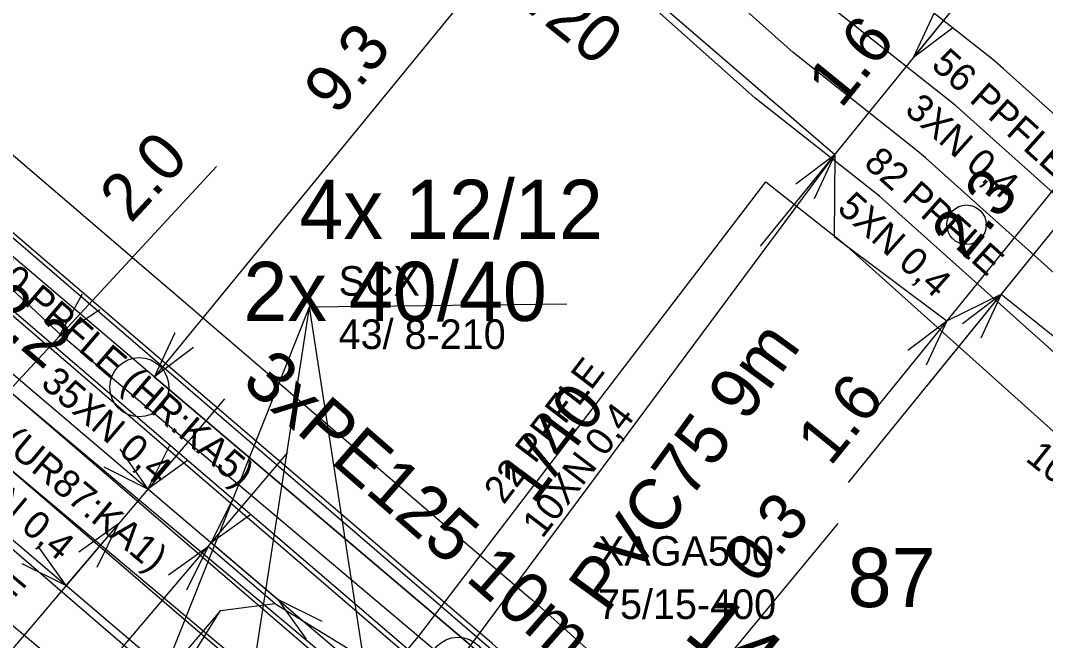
# Model space of a CAD drawing. Extents: x -756413 to -755757, y -1139003 to -1138237.
# Drawn here: x -756288.54 to -756275.54, y -1138375.06 to -1138367.2 of the extents above; entities that cross this region are included whole.
import ezdxf

# ---------------------------------------------------------------- set-up
doc = ezdxf.new("R2010")
doc.units = 0
for name, color, linetype in [('f001_pol_znacky', 7, 'Continuous'), ('f002_inz_znacky_mimo_TO2', 7, 'Continuous'), ('f004_popis_kab_zil', 7, 'Continuous'), ('f004_popisy_mts', 7, 'Continuous'), ('f004_rozvadec_ann', 7, 'Continuous'), ('f006_osa_trasy', 7, 'Continuous'), ('f006_stp_koty', 7, 'Continuous'), ('f006_stp_linie', 7, 'Continuous'), ('f006_stp_texty', 7, 'Continuous'), ('f307_kabel_metal', 7, 'Continuous'), ('f307_kabel_metal_ann', 7, 'Continuous'), ('f307_spojka_metal_ann', 7, 'Continuous'), ('f309_trubka', 7, 'Continuous'), ('f373_cerch_cara', 7, 'Continuous')]:
    doc.layers.add(name, color=color, linetype=linetype)

msp = doc.modelspace()

# ---------------------------------------------------------------- linework, layer by layer
at = {"layer": 'f001_pol_znacky'}
for radius in [0.375, 0.0005]:
    msp.add_circle((-756287.03, -1138371.85), radius, dxfattribs=at)
at = {"layer": 'f002_inz_znacky_mimo_TO2'}
for centre, radius in [((-756276.54, -1138369.79), 0.25), ((-756282.99, -1138375.395), 0.375)]:
    msp.add_circle(centre, radius, dxfattribs=at)
at = {"layer": 'f006_osa_trasy'}
msp.add_line((-756278.21, -1138368.9), (-756282.83, -1138375.12), dxfattribs=at)
for points in [[(-756282.83, -1138375.12), (-756286.84, -1138371.72), (-756290.36, -1138368.73), (-756302.28, -1138358.38), (-756303.67, -1138357.72), (-756311.7, -1138350.6)], [(-756290.62, -1138387.46), (-756284.79, -1138379.7), (-756282.11, -1138376.17), (-756288.02, -1138371.19), (-756301.12, -1138358.98), (-756302.2, -1138358.1), (-756303.05, -1138358.15), (-756304.87, -1138359.66)], [(-756283.96, -1138363.95), (-756281.46, -1138366.1), (-756278.21, -1138368.9)], [(-756278.21, -1138368.9), (-756278.22, -1138369.94), (-756276.79, -1138371.01), (-756276.1, -1138370.67), (-756273.86, -1138372.46), (-756269.86, -1138375.63)], [(-756312.22, -1138404.34), (-756311.43, -1138403.06), (-756307.8, -1138399.78), (-756302.65, -1138394.53), (-756298.44, -1138390.08), (-756293.77, -1138384.84), (-756291.02, -1138381.91), (-756287.55, -1138377.18), (-756286, -1138374.68), (-756285.31, -1138374.59), (-756283.34, -1138375.8)]]:
    msp.add_lwpolyline(points, dxfattribs=at)
at = {"layer": 'f006_stp_koty'}
for p, q in [((-756280.935, -1138364.516), (-756286.839, -1138371.717)), ((-756279.155, -1138370.064), (-756276.267, -1138366.506)), ((-756277.213, -1138367.671), (-756276.287, -1138366.531)), ((-756277.045, -1138371.835), (-756273.672, -1138367.678)), ((-756277.045, -1138371.835), (-756273.672, -1138367.678)), ((-756277.735, -1138372.174), (-756274.424, -1138368.095)), ((-756278.036, -1138373.056), (-756274.175, -1138368.297)), ((-756290.438, -1138373.79), (-756286.053, -1138369.053)), ((-756289.262, -1138371.148), (-756284.127, -1138375.514)), ((-756285.948, -1138371.997), (-756289.156, -1138375.771)), ((-756288.418, -1138376.529), (-756285.145, -1138372.679)), ((-756284.479, -1138377.324), (-756289.103, -1138373.393)), ((-756287.294, -1138373.58), (-756287.961, -1138374.364)), ((-756282.367, -1138378.657), (-756278.169, -1138373.576)), ((-756285.27, -1138374.543), (-756286.117, -1138373.822)), ((-756285.31, -1138374.59), (-756286.157, -1138373.869)), ((-756286, -1138374.68), (-756286.667, -1138375.464))]:
    msp.add_line(p, q, dxfattribs=at)
for points in [[(-756276.717, -1138367.299), (-756277.212, -1138367.671), (-756276.95, -1138367.11)], [(-756278.704, -1138369.271), (-756278.21, -1138368.9), (-756278.471, -1138369.46)], [(-756287.532, -1138370.871), (-756288.05, -1138371.21), (-756287.752, -1138370.667)], [(-756276.594, -1138371.041), (-756276.1, -1138370.67), (-756276.361, -1138371.23)], [(-756277.284, -1138371.381), (-756276.79, -1138371.01), (-756277.051, -1138371.57)], [(-756286.342, -1138371.348), (-756286.839, -1138371.717), (-756286.574, -1138371.157)], [(-756287.279, -1138372.637), (-756286.92, -1138373.14), (-756287.474, -1138372.865)], [(-756286.417, -1138372.78), (-756286.92, -1138373.14), (-756286.645, -1138372.585)], [(-756285.614, -1138373.462), (-756286.117, -1138373.822), (-756285.842, -1138373.267)], [(-756287.796, -1138373.938), (-756287.294, -1138373.579), (-756287.568, -1138374.133)], [(-756288.32, -1138373.861), (-756287.961, -1138374.364), (-756288.515, -1138374.089)], [(-756286.659, -1138374.228), (-756286.157, -1138373.869), (-756286.431, -1138374.423)], [(-756284.909, -1138375.044), (-756285.269, -1138374.542), (-756284.714, -1138374.816)]]:
    msp.add_lwpolyline(points, dxfattribs=at)
at = {"layer": 'f006_stp_linie'}
for points in [[(-756263.68, -1138341.08), (-756271.81, -1138348.33), (-756280.66, -1138356.27), (-756284.45, -1138360.01), (-756285.07, -1138361.43), (-756284.11, -1138363.72), (-756283.96, -1138363.95), (-756281.46, -1138366.1), (-756278.21, -1138368.9), (-756278.22, -1138369.94), (-756276.79, -1138371.01), (-756276.1, -1138370.67), (-756273.86, -1138372.46), (-756269.86, -1138375.63), (-756266.87, -1138377.6), (-756265.9, -1138378.21), (-756263.89, -1138379.52), (-756259.67, -1138381.76), (-756256.89, -1138383.07), (-756253.65, -1138384.58), (-756249.42, -1138386.4), (-756248.03, -1138387), (-756242.76, -1138388.83), (-756238.48, -1138390.05)], [(-756278.21, -1138368.9), (-756282.83, -1138375.12), (-756283.34, -1138375.8)], [(-756286.84, -1138371.72), (-756282.83, -1138375.12), (-756281.82, -1138375.98), (-756280.74, -1138376.82)], [(-756325.53, -1138418.96), (-756324.32, -1138416.51), (-756322.61, -1138413.84), (-756321.49, -1138412.22), (-756320.41, -1138411.21), (-756318.19, -1138409.32), (-756315.85, -1138407.31), (-756315.25, -1138406.9), (-756313.95, -1138405.81), (-756312.72, -1138405.17), (-756312.44, -1138404.71), (-756312.22, -1138404.34), (-756311.43, -1138403.06), (-756307.8, -1138399.78), (-756302.65, -1138394.53), (-756298.44, -1138390.08), (-756293.77, -1138384.84), (-756291.02, -1138381.91), (-756287.55, -1138377.18), (-756286, -1138374.68), (-756285.31, -1138374.59), (-756283.34, -1138375.8), (-756282.74, -1138376.16)]]:
    msp.add_lwpolyline(points, dxfattribs=at)
at = {"layer": 'f307_kabel_metal'}
msp.add_line((-756312.023, -1138350.844), (-756283.054, -1138375.657), dxfattribs=at)
for points in [[(-756263.958, -1138368.536), (-756265.013, -1138368.642), (-756265.349, -1138369.053), (-756270.526, -1138375.388), (-756274.55, -1138372.177), (-756274.944, -1138371.844), (-756277.559, -1138369.503), (-756277.644, -1138369.429), (-756279.221, -1138368.184), (-756286.172, -1138361.983), (-756263.763, -1138340.926)], [(-756263.958, -1138368.536), (-756265.594, -1138368.168), (-756265.806, -1138368.427), (-756265.93, -1138368.578), (-756270.638, -1138374.339), (-756274.074, -1138371.597), (-756274.452, -1138371.278), (-756277.063, -1138368.941), (-756277.165, -1138368.852), (-756278.739, -1138367.609), (-756285.061, -1138361.969), (-756263.157, -1138341.386), (-756259.815, -1138345.149), (-756259.474, -1138344.879)], [(-756263.958, -1138368.536), (-756266.175, -1138367.693), (-756266.325, -1138367.877), (-756266.386, -1138367.951), (-756266.51, -1138368.103), (-756270.75, -1138373.29), (-756273.598, -1138371.017), (-756273.96, -1138370.712), (-756276.566, -1138368.379), (-756276.686, -1138368.275), (-756278.257, -1138367.034), (-756283.95, -1138361.955), (-756263.206, -1138342.461), (-756260.319, -1138345.711), (-756261.071, -1138346.345)], [(-756310.454, -1138350.213), (-756282.069, -1138374.526), (-756282.051, -1138374.542), (-756279.377, -1138376.935), (-756278.838, -1138377.392), (-756272.1, -1138382.766), (-756271.532, -1138383.148), (-756268.323, -1138385.294), (-756262.071, -1138388.934), (-756261.451, -1138389.235), (-756257.195, -1138391.284), (-756251.577, -1138393.575), (-756242.922, -1138395.724), (-756234.355, -1138397.059), (-756233.614, -1138397.174), (-756219.271, -1138399.407)], [(-756310.942, -1138350.783), (-756282.566, -1138375.087), (-756282.554, -1138375.098), (-756279.87, -1138377.5), (-756279.315, -1138377.971), (-756272.544, -1138383.371), (-756271.95, -1138383.771), (-756268.72, -1138385.93), (-756262.424, -1138389.596), (-756261.778, -1138389.91), (-756257.5, -1138391.97), (-756251.81, -1138394.29), (-756243.07, -1138396.46), (-756234.47, -1138397.8), (-756233.729, -1138397.915), (-756219.383, -1138400.149)], [(-756263.958, -1138368.536), (-756266.756, -1138367.218), (-756266.87, -1138367.359), (-756266.905, -1138367.402), (-756266.966, -1138367.475), (-756267.091, -1138367.629), (-756270.862, -1138372.241), (-756273.122, -1138370.437), (-756273.468, -1138370.146), (-756276.07, -1138367.816), (-756276.208, -1138367.697), (-756277.774, -1138366.459), (-756281.626, -1138363.023), (-756280.733, -1138362.088)], [(-756283.971, -1138375.583), (-756283.489, -1138375.009), (-756279.087, -1138369.245), (-756278.124, -1138370.005), (-756278.057, -1138370.064), (-756275.436, -1138372.41), (-756275.026, -1138372.757), (-756270.414, -1138376.436), (-756263.958, -1138368.536)], [(-756284.683, -1138375.264), (-756284.676, -1138375.255), (-756291.577, -1138369.478), (-756295.006, -1138373.564), (-756295.13, -1138373.711), (-756298.544, -1138377.773), (-756318.688, -1138398.187), (-756319.519, -1138397.43)], [(-756285.765, -1138375.387), (-756285.733, -1138375.348), (-756291.484, -1138370.534), (-756294.432, -1138374.047), (-756294.556, -1138374.194), (-756297.989, -1138378.278), (-756318.66, -1138399.227), (-756319.205, -1138399.742), (-756330.074, -1138410.117), (-756326.605, -1138419.746), (-756341.343, -1138432.472)], [(-756286.972, -1138375.658), (-756286.816, -1138375.476), (-756291.179, -1138371.724), (-756291.391, -1138371.59), (-756293.858, -1138374.53), (-756293.982, -1138374.677), (-756297.434, -1138378.783), (-756318.135, -1138399.763), (-756318.689, -1138400.286), (-756329.203, -1138410.322), (-756325.725, -1138419.977), (-756325.47, -1138420.682), (-756325.148, -1138421.576), (-756313.125, -1138448.388), (-756305.964, -1138469.586), (-756306.39, -1138472.389), (-756307.168, -1138474.638), (-756308.162, -1138475.59), (-756309.285, -1138475.849), (-756315.462, -1138479.353)], [(-756288.384, -1138376.174), (-756287.902, -1138375.6), (-756287.847, -1138375.534), (-756291.298, -1138372.646), (-756293.284, -1138375.013), (-756293.408, -1138375.16), (-756296.879, -1138379.289), (-756317.519, -1138400.206), (-756328.332, -1138410.527), (-756324.452, -1138421.295), (-756312.811, -1138447.256), (-756304.831, -1138441.703), (-756301.921, -1138444.882), (-756300.466, -1138443.292)]]:
    msp.add_lwpolyline(points, dxfattribs=at)
at = {"layer": 'f309_trubka'}
for points in [[(-756310.552, -1138351.565), (-756303.608, -1138357.783), (-756301.98, -1138358.543), (-756289.41, -1138369.29), (-756273.581, -1138382.899), (-756267.391, -1138386.699), (-756260.769, -1138390.604), (-756251.313, -1138394.329), (-756242.348, -1138396.659), (-756226.133, -1138399.092), (-756211.588, -1138401.296), (-756190.711, -1138405.458), (-756180.192, -1138409.372), (-756170.888, -1138414.389), (-756161.932, -1138421.301), (-756154.261, -1138427.534)], [(-756311.061, -1138352.116), (-756304.026, -1138358.416), (-756302.39, -1138359.179), (-756289.898, -1138369.859), (-756274.024, -1138383.507), (-756267.778, -1138387.342), (-756261.099, -1138391.28), (-756251.546, -1138395.043), (-756242.498, -1138397.395), (-756226.245, -1138399.834), (-756211.718, -1138402.035), (-756190.916, -1138406.182), (-756180.502, -1138410.057), (-756171.298, -1138415.02), (-756162.398, -1138421.889), (-756154.878, -1138427.999)], [(-756311.57, -1138352.667), (-756304.444, -1138359.049), (-756302.8, -1138359.815), (-756290.386, -1138370.428), (-756274.468, -1138384.115), (-756268.165, -1138387.985), (-756261.429, -1138391.956), (-756251.779, -1138395.757), (-756242.648, -1138398.131), (-756226.357, -1138400.576), (-756211.848, -1138402.774), (-756191.121, -1138406.906), (-756180.812, -1138410.742), (-756171.708, -1138415.651), (-756162.864, -1138422.477), (-756155.495, -1138428.464)], [(-756312.079, -1138353.218), (-756304.862, -1138359.682), (-756303.21, -1138360.452), (-756290.874, -1138370.997), (-756274.912, -1138384.723), (-756268.552, -1138388.628), (-756261.759, -1138392.632), (-756252.012, -1138396.471), (-756242.798, -1138398.867), (-756226.469, -1138401.318), (-756211.978, -1138403.513), (-756191.326, -1138407.63), (-756181.122, -1138411.427), (-756172.118, -1138416.282), (-756163.33, -1138423.065), (-756156.112, -1138428.929), (-756154.994, -1138431.554)]]:
    msp.add_lwpolyline(points, dxfattribs=at)
at = {"layer": 'f373_cerch_cara'}
for p in [(-756286.785, -1138375.642), (-756285.576, -1138375.389)]:
    msp.add_line(p, (-756284.874, -1138370.831), dxfattribs=at)
msp.add_lwpolyline([(-756284.151, -1138375.531), (-756284.874, -1138370.831), (-756281.608, -1138370.792)], dxfattribs=at)

# ---------------------------------------------------------------- texts
at = {"layer": 'f004_popis_kab_zil'}
for s, rotation, p in [('3/12, 1/20', 321.17, (-756284, -1138365.56)), ('1/40', 53.37, (-756282.03, -1138373.35))]:
    msp.add_text(s, height=0.6, rotation=rotation, dxfattribs=at).set_placement(p)
at = {"layer": 'f004_popisy_mts'}
for s, p in [('4x 12/12', (-756285, -1138369.97)), ('2x 40/40', (-756285.71, -1138371.01))]:
    msp.add_text(s, height=0.75, dxfattribs=at).set_placement(p)
msp.add_text('140-20/60/60', height=0.75, rotation=321.28, dxfattribs=at).set_placement((-756280.15, -1138375.01))
at = {"layer": 'f004_rozvadec_ann'}
msp.add_text('87', height=0.75, dxfattribs=at).set_placement((-756278.049, -1138374.637))
at = {"layer": 'f006_stp_koty'}
for s, rotation, p in [('1.6', 50.94, (-756278.133, -1138368.33)), ('9.3', 50.65, (-756284.523, -1138368.419)), ('2.0', 47.21, (-756287.14, -1138369.785)), ('2.3', 50.94, (-756276.564, -1138370.256)), ('2.2', 319.63, (-756289.067, -1138370.919)), ('1.6', 50.94, (-756278.268, -1138372.866)), ('0.3', 50.43, (-756279.212, -1138374.367))]:
    msp.add_text(s, height=0.6, rotation=rotation, dxfattribs=at).set_placement(p)
at = {"layer": 'f006_stp_texty'}
for s, rotation, p in [('PVC75 9m', 53.97, (-756281.1, -1138374.73)), ('3xPE125 10m', 318.91, (-756285.75, -1138371.81))]:
    msp.add_text(s, height=0.65, rotation=rotation, dxfattribs=at).set_placement(p)
at = {"layer": 'f307_kabel_metal_ann'}
for s, rotation, p in [('56 PPFLE', 318.16, (-756277.003, -1138367.786)), (' 3XN 0,4', 318.16, (-756277.437, -1138368.27)), ('82 PPFLE', 318.16, (-756277.859, -1138369.033)), (' 5XN 0,4', 318.16, (-756278.293, -1138369.517)), ('40 PPFLE (HR:KA5)', 319.42, (-756289.003, -1138370.364)), ('85 PPFLE (UR87:KA1)', 320.07, (-756290.533, -1138371.135)), ('22 PPFLE', 52.63, (-756282.409, -1138373.348)), (' 35XN 0,4', 319.42, (-756288.394, -1138371.741)), (' 10XN 0,4', 52.63, (-756281.999, -1138373.881)), (' 10XN 0,4', 320.07, (-756289.642, -1138372.728)), (' 10XN 0,4', 321.42, (-756275.909, -1138372.692)), ('109 PPFLE', 320.08, (-756290.499, -1138373.12))]:
    msp.add_text(s, height=0.35, rotation=rotation, dxfattribs=at).set_placement(p)
at = {"layer": 'f307_spojka_metal_ann'}
for s, p in [('SCX', (-756284.503, -1138370.69)), ('43/ 8-210', (-756284.503, -1138371.365)), ('XAGA500', (-756281.214, -1138374.113)), ('75/15-400', (-756281.214, -1138374.788))]:
    msp.add_text(s, height=0.375, dxfattribs=at).set_placement(p)

doc.saveas('drawing.dxf')
